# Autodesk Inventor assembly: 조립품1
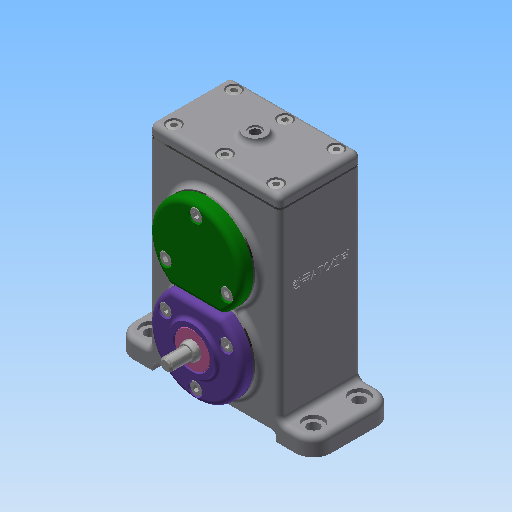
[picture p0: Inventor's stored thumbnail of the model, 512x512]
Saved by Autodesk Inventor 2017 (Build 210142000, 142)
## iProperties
Part Number: 조립품1
Material: 일반
Document SubType Name: Assembly
Designer: mrc
Author: mrc
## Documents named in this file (24)
- C:\Users\mrc\Desktop\600506V1010\조립품1.iam
- C:\Users\mrc\Desktop\600506V1010\개스킷 A.ipt
- C:\Users\mrc\Desktop\600506V1010\개스킷 B.ipt
- C:\Users\mrc\Desktop\600506V1010\개스킷 C.ipt
- C:\Users\mrc\Desktop\600506V1010\베어링 6001.ipt
- 베어링 6001.ipt
- C:\Users\mrc\Desktop\600506V1010\베어링 6002.ipt
- 베어링 6002.ipt
- C:\Users\mrc\Desktop\600506V1010\본체.ipt
- C:\Users\mrc\Desktop\600506V1010\볼트 M4.ipt
- C:\Users\mrc\Desktop\600506V1010\스퍼기어 A.ipt
- C:\Users\mrc\Desktop\600506V1010\스퍼기어 B.ipt
- C:\Users\mrc\Desktop\600506V1010\오일 실 10 20 7.ipt
- C:\Users\mrc\Desktop\600506V1010\오일 실 12 22 7.ipt
- C:\Users\mrc\Desktop\600506V1010\축 A.ipt
- C:\Users\mrc\Desktop\600506V1010\축 B.ipt
- C:\Users\mrc\Desktop\600506V1010\칼라.ipt
- C:\Users\mrc\Desktop\600506V1010\커버 A.ipt
- C:\Users\mrc\Desktop\600506V1010\커버 B.ipt
- C:\Users\mrc\Desktop\600506V1010\커버 C.ipt
- C:\Users\mrc\Desktop\600506V1010\커버 D.ipt
- C:\Users\mrc\Desktop\600506V1010\커버 E.ipt
- C:\Users\mrc\Desktop\600506V1010\키 4 x 4 x 12.ipt
- C:\Users\mrc\Desktop\600506V1010\키 5 x 5 x 12.ipt
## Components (5 placed, 3 different names)
1. 개스킷 A:1
2. 개스킷 B:1
3. 개스킷 C:1
4. 개스킷 B:2
5. 개스킷 B:3
